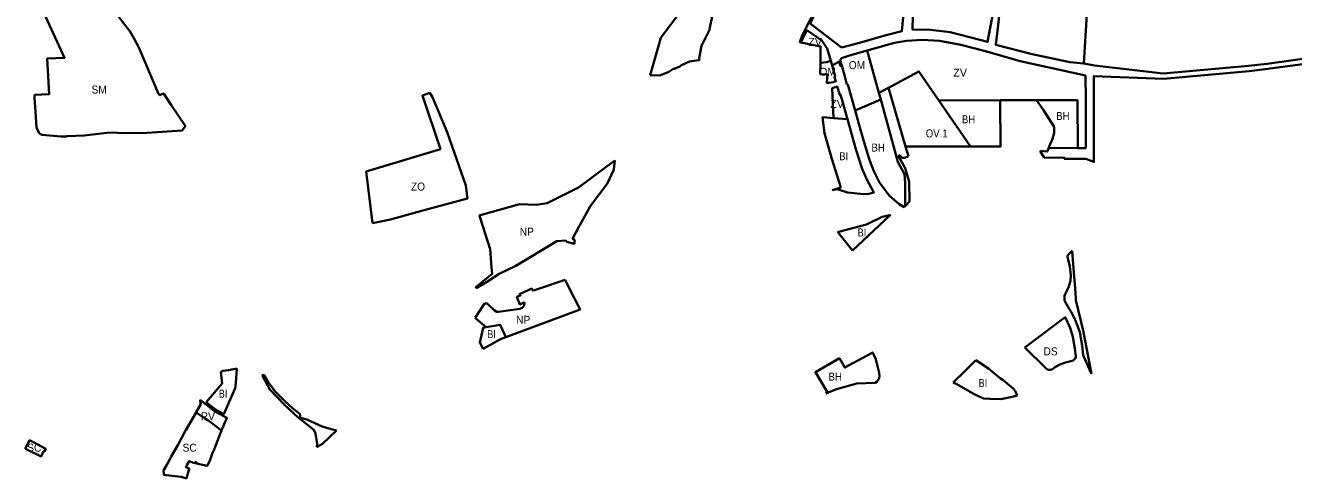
# Model space of a CAD drawing. Extents: x -650971 to -642489, y -1074311 to -1062745.
# Drawn here: x -647057 to -645155, y -1070613 to -1069933 of the extents above; entities that cross this region are included whole.
import ezdxf

# ---------------------------------------------------------------- set-up
doc = ezdxf.new("R2010")
doc.units = 0
doc.header["$LTSCALE"] = 4.8
for name, color, linetype, lineweight in [('1', 7, 'Continuous', 35), ('11', 7, 'Continuous', 35), ('12', 7, 'Continuous', 35), ('15', 7, 'Continuous', 35), ('17', 7, 'Continuous', 35), ('18', 7, 'Continuous', 35), ('2', 7, 'Continuous', 35), ('24', 7, 'Continuous', 35), ('40', 7, 'Continuous', 35), ('42', 7, 'Continuous', 35), ('48', 7, 'Continuous', 35), ('62', 7, 'Continuous', 35)]:
    doc.layers.add(name, color=color, linetype=linetype, lineweight=lineweight)

msp = doc.modelspace()

# ---------------------------------------------------------------- linework, layer by layer
at = {"layer": '1'}
for p, q in [((-645812.76, -1070060.53), (-645774.423, -1070044.167)), ((-645687.31, -1070045.724), (-645595.2, -1070045.403))]:
    msp.add_line(p, q, dxfattribs=at)
for points in [[(-645791.72, -1070133.09), (-645797.66, -1070113.88), (-645804.52, -1070089.63), (-645812.76, -1070060.53)], [(-645774.423, -1070044.167), (-645748.62, -1070137.889), (-645738.79, -1070156.281), (-645737.624, -1070169.544), (-645737.756, -1070204.389), (-645739.12, -1070205.9)], [(-645595.2, -1070045.403), (-645594.733, -1070114.868), (-645639.641, -1070114.891), (-645687.31, -1070045.724)], [(-645540.678, -1070045.406), (-645479.429, -1070045.409), (-645478.664, -1070117.114), (-645522.587, -1070116.952)], [(-645522.587, -1070116.952), (-645521.73, -1070114.83), (-645518.35, -1070106.87), (-645517.02, -1070103.08), (-645514.61, -1070094.35), (-645514.56, -1070090.91), (-645514.49, -1070085.4), (-645530.3, -1070060.08), (-645540.678, -1070045.406)], [(-645784.83, -1070151.9), (-645790.77, -1070136.14), (-645791.72, -1070133.09)], [(-645739.12, -1070205.9), (-645746.73, -1070201.04), (-645761.78, -1070188.29), (-645776.26, -1070168.94), (-645784.83, -1070151.9)], [(-645788.461, -1070424.668), (-645786.9, -1070423.81), (-645782.13, -1070432.59), (-645776.95, -1070454.51), (-645776.04, -1070459.38)], [(-645856.87, -1070485.24), (-645853.98, -1070483.81), (-645862.66, -1070469.5), (-645872.35, -1070453.55), (-645836.32, -1070432.55), (-645828.24, -1070446.54), (-645788.46, -1070424.67), (-645788.461, -1070424.668)], [(-645776.04, -1070459.38), (-645776.96, -1070462.56), (-645777.8, -1070464.4)], [(-645810.44, -1070470.17), (-645840.59, -1070479), (-645856.87, -1070485.24)], [(-645777.8, -1070464.4), (-645780.38, -1070467.64), (-645782.57, -1070469.22), (-645810.44, -1070470.17)]]:
    msp.add_lwpolyline(points, dxfattribs=at)
at = {"layer": '11'}
msp.add_lwpolyline([(-645762.868, -1070026.606), (-645717.36, -1070002.12), (-645687.31, -1070045.724), (-645639.641, -1070114.891), (-645737.075, -1070114.955)], close=True, dxfattribs=at)
at = {"layer": '12'}
for points in [[(-645864.77, -1069989.26), (-645855.54, -1069988.24), (-645849.1, -1069986.42), (-645847.14, -1069993.34), (-645844.102, -1070004.015)], [(-645833.32, -1069991.86), (-645835, -1069985), (-645833, -1069982), (-645821, -1069978), (-645794.679, -1069970.596), (-645777.143, -1070034.287), (-645774.423, -1070044.167), (-645812.76, -1070060.53)], [(-645855.168, -1070019.44), (-645855.17, -1070019.44), (-645854.42, -1070006.47), (-645864.97, -1070006.16), (-645864.77, -1069989.26)], [(-645844.102, -1070004.015), (-645843.22, -1070007.12), (-645842.8, -1070008.59)], [(-645825.08, -1070021.52), (-645828.9, -1070007.76), (-645833.32, -1069991.86)], [(-645841.92, -1070017.321), (-645841.89, -1070017.42), (-645845.17, -1070017.91), (-645845.14, -1070018.08), (-645845.37, -1070018.12), (-645852.33, -1070019.2), (-645852.36, -1070019.01), (-645855.168, -1070019.44)], [(-645842.8, -1070008.59), (-645843.94, -1070010.6), (-645841.92, -1070017.321)], [(-645812.76, -1070060.53), (-645823.76, -1070021.67), (-645825.08, -1070021.52)]]:
    msp.add_lwpolyline(points, dxfattribs=at)
at = {"layer": '15'}
msp.add_line((-646701.65, -1070457.93), (-646699.26, -1070457.2), dxfattribs=at)
for points in [[(-645857.204, -1069862.954), (-645857.289, -1069863.338), (-645863.95, -1069889.468), (-645869.262, -1069905.935), (-645874.219, -1069917.496), (-645880.431, -1069930.3), (-645833, -1069966), (-645806, -1069959), (-645768.424, -1069948.431), (-645742.967, -1069941.862), (-645738.039, -1069894.231), (-645729.006, -1069844.136), (-645777.852, -1069832.241), (-645804.185, -1069825.84), (-645804.28, -1069826.76)], [(-645894.25, -1069958.7), (-645895.66, -1069958.42), (-645892.09, -1069947.98), (-645876.15, -1069916.47), (-645870.89, -1069903.5), (-645865.78, -1069888.76), (-645858.78, -1069862.84), (-645857.204, -1069862.954)], [(-645464.288, -1069895.362), (-645492.842, -1069895), (-645526.451, -1069890.745), (-645589.84, -1069875.892), (-645594.866, -1069902.242), (-645596.463, -1069914.335), (-645598.491, -1069932.472), (-645601.753, -1069962.317), (-645547.4, -1069976.382), (-645490.814, -1069988.074), (-645469.701, -1069990.011)], [(-645849.1, -1069986.42), (-645854.81, -1069967.927), (-645862.782, -1069955.809), (-645885.422, -1069940.184), (-645894.25, -1069958.7)], [(-645478.664, -1070117.114), (-645466.96, -1070117.157), (-645467.068, -1070044.959), (-645467.472, -1070008.38), (-645565.133, -1069986.508), (-645617.403, -1069971.714), (-645654.145, -1069962.232), (-645686.147, -1069956.306), (-645712.222, -1069954.725), (-645735.532, -1069956.306), (-645753.706, -1069959.071), (-645794.679, -1069970.596)], [(-645794.679, -1069970.596), (-645821, -1069978), (-645833, -1069982), (-645835, -1069985), (-645833.32, -1069991.86), (-645834.65, -1069994.21), (-645836.64, -1069987.18), (-645847.14, -1069993.34), (-645849.1, -1069986.42)], [(-645004.791, -1070324.889), (-645034.122, -1070126.616), (-645043.92, -1070076.344), (-645050.293, -1070047.035), (-645056.555, -1070026.163), (-645065.235, -1070011.695), (-645086.484, -1069984.195), (-645123.206, -1069988.629), (-645194.003, -1069998.417), (-645221.99, -1070001.66), (-645350.591, -1070013.242), (-645455.073, -1070009.111), (-645454.881, -1070137.836), (-645466.862, -1070133.219), (-645499.142, -1070133.293)], [(-645469.701, -1069990.011), (-645453.852, -1069992.968), (-645350.784, -1070005.227), (-645222.809, -1069993.701), (-645195.011, -1069990.48), (-645124.233, -1069980.695), (-645064.052, -1069973.429)], [(-645777.143, -1070034.287), (-645762.868, -1070026.606), (-645737.075, -1070114.955), (-645732.91, -1070129.5)], [(-645737.756, -1070204.389), (-645737.624, -1070169.544), (-645738.79, -1070156.281), (-645748.62, -1070137.889), (-645774.423, -1070044.167), (-645777.143, -1070034.287)], [(-645534.63, -1070121.09), (-645524.82, -1070122.48), (-645522.587, -1070116.952), (-645478.664, -1070117.114)], [(-645732.91, -1070129.5), (-645734.77, -1070130.18), (-645737.48, -1070131.45), (-645738.41, -1070131.78), (-645739.41, -1070131.93), (-645740.89, -1070131.8), (-645741.83, -1070131.53), (-645742.67, -1070131.07), (-645743.87, -1070130.15), (-645744.73, -1070129), (-645745.29, -1070127.83), (-645747.67, -1070129.14), (-645737.63, -1070147.39), (-645731.94, -1070167.87), (-645731.3, -1070197.24), (-645737.756, -1070204.389)], [(-645529.17, -1070131.4), (-645534.7, -1070122.95), (-645534.63, -1070121.09)], [(-645499.142, -1070133.293), (-645499.276, -1070131.652), (-645529.17, -1070131.4)], [(-645491.97, -1070358.14), (-645496.02, -1070351.15), (-645498, -1070347.74), (-645498.74, -1070345.87), (-645499.09, -1070343.91), (-645499.01, -1070340.96), (-645498.75, -1070338.98), (-645497.83, -1070336.16), (-645496.12, -1070332.34), (-645495.44, -1070330.67), (-645493.05, -1070326.11), (-645490.03, -1070316.27), (-645489.31, -1070307.77), (-645490.79, -1070294.93), (-645494.12, -1070282.52), (-645494.57, -1070280.34), (-645493.8, -1070277.67), (-645491.94, -1070275.85), (-645487.361, -1070271.37)], [(-645487.361, -1070271.37), (-645485.21, -1070298.03), (-645484.27, -1070309.7), (-645483.34, -1070321.17), (-645481.65, -1070342.07), (-645481.67, -1070345.39), (-645471, -1070391), (-645458.32, -1070455.91)], [(-645458.32, -1070455.91), (-645461.32, -1070449.31), (-645470.99, -1070428.07), (-645472.61, -1070413.13), (-645476.12, -1070393.13), (-645482.16, -1070375.96), (-645488.99, -1070362.96), (-645491.97, -1070358.14)], [(-646643.895, -1070524.284), (-646647.226, -1070521.673), (-646668.361, -1070502.459), (-646690.316, -1070479.212), (-646693.119, -1070474.009), (-646701.65, -1070457.93)], [(-646699.26, -1070457.2), (-646692.74, -1070468.28), (-646681.6, -1070482.89), (-646667.42, -1070497.28)], [(-646800.94, -1070514.04), (-646800.6, -1070513.43), (-646793.75, -1070501.26), (-646794.53, -1070495.7), (-646794.59, -1070494.62)], [(-646794.59, -1070494.62), (-646773, -1070511.96), (-646770.95, -1070512.94), (-646765.96, -1070515.75), (-646754.52, -1070522.08), (-646755.84, -1070524.5), (-646762.71, -1070540.85)], [(-646667.42, -1070497.28), (-646656.83, -1070506.66), (-646656.09, -1070507.31)], [(-646762.71, -1070540.85), (-646779.68, -1070527.87), (-646782.63, -1070526.02), (-646788, -1070522.49), (-646800.94, -1070514.04)], [(-646656.09, -1070507.31), (-646653.87, -1070509.28), (-646645.31, -1070515.85), (-646644.2, -1070522.08)], [(-646644.2, -1070522.08), (-646634.85, -1070524.43), (-646611.88, -1070534.82), (-646599.81, -1070538.51), (-646590.2, -1070540.66)], [(-646619.99, -1070565.54), (-646619.34, -1070560.95), (-646621.729, -1070545.248), (-646624.211, -1070539.711), (-646643.895, -1070524.284)], [(-646590.2, -1070540.66), (-646611.41, -1070560.96), (-646619.15, -1070565.53), (-646619.99, -1070565.54)]]:
    msp.add_lwpolyline(points, dxfattribs=at)
msp.add_lwpolyline([(-645599.271, -1069873.685), (-645677.849, -1069855.3), (-645716.277, -1069847.01), (-645723.668, -1069891.356), (-645726.131, -1069918.457), (-645726.542, -1069939.398), (-645699.889, -1069939.714), (-645670.325, -1069943.002), (-645625.979, -1069954.92), (-645614.072, -1069957.797), (-645606.07, -1069913.163), (-645604.424, -1069900.701)], close=True, dxfattribs=at)
at = {"layer": '17'}
msp.add_line((-646849.59, -1070607.4), (-646848.99, -1070606.28), dxfattribs=at)
for points in [[(-646816.42, -1070540.49), (-646802.19, -1070516.26), (-646800.94, -1070514.04)], [(-646800.94, -1070514.04), (-646788, -1070522.49), (-646782.63, -1070526.02), (-646779.68, -1070527.87), (-646762.71, -1070540.85)], [(-646848.99, -1070606.28), (-646849.72, -1070600.98), (-646844.76, -1070592.54), (-646841.16, -1070585.79), (-646838.95, -1070581.53), (-646838.05, -1070579.93), (-646828.45, -1070562.89), (-646816.6, -1070540.84), (-646816.42, -1070540.49)], [(-646762.71, -1070540.85), (-646763.68, -1070543.15), (-646764.24, -1070544.5), (-646768.86, -1070556.21), (-646771.17, -1070562.7), (-646774.91, -1070571.88), (-646775.25, -1070572.39)], [(-646775.25, -1070572.39), (-646776.04, -1070574.27), (-646779.9, -1070584.92), (-646783.59, -1070593.52), (-646784, -1070593.34), (-646784.18, -1070593.76), (-646800.47, -1070590.28), (-646800.13, -1070588.71), (-646801.73, -1070588.37), (-646802.06, -1070589.93), (-646806.41, -1070589), (-646811.06, -1070586.67), (-646814.52, -1070592.78), (-646816.11, -1070595.8), (-646814.95, -1070596.36), (-646810.82, -1070598.23), (-646811.5, -1070600.29), (-646812.5, -1070603.78), (-646813.97, -1070608.7), (-646815.05, -1070613.14)], [(-646815.05, -1070613.14), (-646822.99, -1070610.51), (-646827.88, -1070610.12), (-646849.59, -1070607.4)]]:
    msp.add_lwpolyline(points, dxfattribs=at)
msp.add_lwpolyline([(-647055.79, -1070569.07), (-647056.8, -1070568.32), (-647056.79, -1070567.41), (-647052.77, -1070559.7), (-647051.14, -1070556.59), (-647050.37, -1070555.74), (-647049.52, -1070555.64), (-647026.14, -1070568.26), (-647028.52, -1070572.63), (-647029.44, -1070572.13), (-647033.01, -1070579.83)], close=True, dxfattribs=at)
at = {"layer": '18'}
for points in [[(-647043.25, -1070037.29), (-647021.27, -1070036.28), (-647024.05, -1069982.48), (-646998.06, -1069981.49), (-647034.51, -1069902.21)], [(-646931.67, -1069902.89), (-646922.79, -1069912.31), (-646909.48, -1069929.65), (-646900.26, -1069941.64), (-646894.42, -1069952.39), (-646886.85, -1069966.26), (-646857.06, -1070035.86), (-646855.62, -1070037.66), (-646849.79, -1070035.17), (-646849.33, -1070035.63), (-646837.65, -1070053.22), (-646816.9, -1070084.45), (-646817.15, -1070084.76)], [(-647036.03, -1070094.96), (-647040.12, -1070086.11), (-647040.92, -1070070.85), (-647041.53, -1070062.28), (-647043.03, -1070042.14), (-647043.25, -1070037.29)], [(-646817.15, -1070084.76), (-646821.89, -1070090.7), (-646859.29, -1070093.1), (-646874.9, -1070094.1), (-646904.97, -1070094.52), (-646918.75, -1070094.08), (-646925.08, -1070093.82), (-646934.63, -1070094.24), (-646968.89, -1070098.02), (-646993.92, -1070099.49), (-646995.86, -1070099.52), (-647003.49, -1070099.66), (-647031.73, -1070097.21), (-647034.17, -1070096.49), (-647036.03, -1070094.96)]]:
    msp.add_lwpolyline(points, dxfattribs=at)
at = {"layer": '2'}
msp.add_line((-645665.6, -1070469.04), (-645648.9, -1070452.38), dxfattribs=at)
for points in [[(-645804.28, -1069826.76), (-645804.185, -1069825.84), (-645777.852, -1069832.241), (-645729.006, -1069844.136), (-645738.039, -1069894.231), (-645742.967, -1069941.862), (-645768.424, -1069948.431), (-645806, -1069959), (-645833, -1069966), (-645880.431, -1069930.3), (-645874.219, -1069917.496), (-645869.262, -1069905.935), (-645863.95, -1069889.468), (-645857.289, -1069863.338), (-645857.204, -1069862.954)], [(-645469.701, -1069990.011), (-645490.814, -1069988.074), (-645547.4, -1069976.382), (-645601.753, -1069962.317), (-645598.491, -1069932.472), (-645596.463, -1069914.335), (-645594.866, -1069902.242), (-645589.84, -1069875.892), (-645526.451, -1069890.745), (-645492.842, -1069895), (-645464.288, -1069895.362)], [(-645464.288, -1069895.362), (-645464.206, -1069899.449), (-645469.701, -1069990.011)], [(-645858.53, -1070094.64), (-645861.74, -1070070.95), (-645855.28, -1070071.32), (-645845.01, -1070072.12), (-645824.28, -1070073.67), (-645811.48, -1070118.65), (-645801.99, -1070148.51), (-645795.07, -1070164.26), (-645784.51, -1070183.77), (-645792.37, -1070186.01)], [(-645847.2, -1070180.14), (-645834.31, -1070176.15), (-645847.88, -1070133.4), (-645858.53, -1070094.64)], [(-645792.37, -1070186.01), (-645799.91, -1070186.32), (-645824.12, -1070183.63), (-645839.82, -1070178.94), (-645847.2, -1070180.14)], [(-645833.92, -1070241.96), (-645795.85, -1070231.81), (-645772.08, -1070220.39), (-645760.91, -1070217.98)], [(-645760.91, -1070217.98), (-645760.05, -1070217.79), (-645816.9, -1070270.96)], [(-645816.9, -1070270.96), (-645838.53, -1070243.19), (-645833.92, -1070241.96)], [(-646370.56, -1070418.29), (-646375.63, -1070408.76), (-646370.61, -1070386.73), (-646365.7, -1070385.89)], [(-646365.7, -1070385.89), (-646344.93, -1070382.33), (-646336.35, -1070400.9)], [(-646336.35, -1070400.9), (-646344.26, -1070403.84), (-646370.56, -1070418.29)], [(-645648.9, -1070452.38), (-645636.42, -1070439.93), (-645631.63, -1070435.3)], [(-645631.63, -1070435.3), (-645612.77, -1070447.82), (-645594.62, -1070462.7), (-645590.966, -1070465.607), (-645575.7, -1070477.77), (-645572.86, -1070481.41), (-645569.97, -1070488.3)], [(-646785.5, -1070498.47), (-646785.15, -1070498.05), (-646761.8, -1070470.4), (-646763.94, -1070452.95)], [(-646763.94, -1070452.95), (-646760.03, -1070451.56), (-646752.29, -1070450.28), (-646739.74, -1070447.98)], [(-646739.74, -1070447.98), (-646741.33, -1070469.79), (-646742.37, -1070477.2), (-646747.89, -1070489.87), (-646759.42, -1070516.37)], [(-645569.97, -1070488.3), (-645571.13, -1070488.89), (-645577.47, -1070490.3), (-645594.41, -1070494.08), (-645610.16, -1070493.43), (-645611.52, -1070493.37), (-645620.22, -1070493), (-645633.35, -1070486.91), (-645660.29, -1070471.12), (-645665.6, -1070469.04)], [(-646759.42, -1070516.37), (-646771.9, -1070509.4), (-646785.5, -1070498.47)]]:
    msp.add_lwpolyline(points, dxfattribs=at)
msp.add_lwpolyline([(-645599.271, -1069873.685), (-645604.424, -1069900.701), (-645606.07, -1069913.163), (-645614.072, -1069957.797), (-645625.979, -1069954.92), (-645670.325, -1069943.002), (-645699.889, -1069939.714), (-645726.542, -1069939.398), (-645726.131, -1069918.457), (-645723.668, -1069891.356), (-645716.277, -1069847.01), (-645677.849, -1069855.3)], close=True, dxfattribs=at)
at = {"layer": '24'}
for points in [[(-645558.36, -1070416.1), (-645497.81, -1070370.93), (-645490.19, -1070386.97)], [(-645490.19, -1070386.97), (-645486.54, -1070400.38), (-645483.29, -1070417.99)], [(-645483.29, -1070417.99), (-645481.93, -1070430.04), (-645482.18, -1070432.13), (-645485.67, -1070435.7), (-645489.34, -1070437.05), (-645497.33, -1070438.82), (-645505.88, -1070441.74), (-645513.81, -1070446.24), (-645517.44, -1070449.23), (-645517.95, -1070449.45), (-645520.4, -1070449.87), (-645521.41, -1070449.84), (-645522.95, -1070449.61), (-645524.42, -1070449.16), (-645525.75, -1070448.41), (-645527.34, -1070447.1), (-645558.36, -1070416.1)]]:
    msp.add_lwpolyline(points, dxfattribs=at)
at = {"layer": '40'}
for points in [[(-645894.25, -1069958.7), (-645885.422, -1069940.184), (-645862.782, -1069955.809), (-645854.81, -1069967.927), (-645849.1, -1069986.42)], [(-645864.77, -1069989.26), (-645864.48, -1069964.53), (-645894.25, -1069958.7)], [(-645794.679, -1069970.596), (-645753.706, -1069959.071), (-645735.532, -1069956.306), (-645712.222, -1069954.725), (-645686.147, -1069956.306), (-645654.145, -1069962.232), (-645617.403, -1069971.714), (-645565.133, -1069986.508), (-645467.472, -1070008.38), (-645467.068, -1070044.959), (-645466.96, -1070117.157), (-645478.664, -1070117.114)], [(-645849.1, -1069986.42), (-645855.54, -1069988.24), (-645864.77, -1069989.26)], [(-645687.31, -1070045.724), (-645717.36, -1070002.12), (-645762.868, -1070026.606), (-645777.143, -1070034.287), (-645794.679, -1069970.596)], [(-645540.678, -1070045.406), (-645547.768, -1070045.237), (-645595.2, -1070045.403), (-645687.31, -1070045.724)], [(-645478.664, -1070117.114), (-645479.429, -1070045.409), (-645540.678, -1070045.406)]]:
    msp.add_lwpolyline(points, dxfattribs=at)
msp.add_lwpolyline([(-645847.08, -1070027.09), (-645839.641, -1070024.9), (-645835.91, -1070037.31), (-645834.8, -1070036.71), (-645824.28, -1070073.67), (-645845.01, -1070072.12)], close=True, dxfattribs=at)
at = {"layer": '42'}
for points in [[(-646536.47, -1070229.65), (-646545.78, -1070152.41), (-646434.503, -1070118.512), (-646461.415, -1070037.991), (-646450.22, -1070034.31)], [(-646450.22, -1070034.31), (-646446.21, -1070040.55), (-646424.17, -1070093.21), (-646417.23, -1070113.25), (-646396.51, -1070173.06), (-646393.97, -1070192.69), (-646460.8, -1070210.57), (-646509.31, -1070224.11), (-646536.47, -1070229.65)]]:
    msp.add_lwpolyline(points, dxfattribs=at)
at = {"layer": '48'}
for points in [[(-646119.95, -1070007.73), (-646104.04, -1069951.75), (-646077.78, -1069916.11)], [(-646027.3, -1069919.47), (-646030.62, -1069936.3), (-646031.24, -1069939.45), (-646043.2, -1069963.46), (-646046.63, -1069982.04), (-646046.28, -1069985.18)], [(-646046.28, -1069985.18), (-646050.68, -1069985.78), (-646060.94, -1069987.19), (-646073.1, -1069992.61), (-646075.69, -1069994.68), (-646083.67, -1069998.4), (-646084.39, -1069997.53), (-646091.87, -1070002.66), (-646105.35, -1070008.18), (-646119.95, -1070007.73)], [(-646376.5, -1070218.32), (-646315.95, -1070201.09), (-646291.14, -1070202.1), (-646274.26, -1070199.6), (-646227.29, -1070176.24), (-646173.2, -1070135.64)], [(-646173.2, -1070135.64), (-646174.62, -1070149.28), (-646184.67, -1070170.61), (-646209.55, -1070203.85), (-646225.7, -1070232.93), (-646226.42, -1070234.23), (-646236.44, -1070253.13), (-646233.06, -1070254.74), (-646233.36, -1070257.04), (-646233.69, -1070259.57)], [(-646380.69, -1070327.47), (-646381.25, -1070325.85), (-646356.8, -1070305.73), (-646357.73, -1070296.13), (-646359.89, -1070269.01), (-646375.52, -1070220.21), (-646376.5, -1070218.32)], [(-646233.69, -1070259.57), (-646234.17, -1070260.88), (-646245.02, -1070257.65), (-646246.71, -1070255.96), (-646259.91, -1070256.89), (-646321.24, -1070293.85), (-646346.57, -1070305.88), (-646365.63, -1070318.37), (-646380.69, -1070327.47)], [(-646382.67, -1070371.94), (-646368.4, -1070350.41), (-646364.34, -1070350.19), (-646353.81, -1070360.18), (-646349.76, -1070362.69), (-646347.49, -1070363.01), (-646315.7, -1070358.27), (-646314.6, -1070358.05), (-646311.82, -1070356.89), (-646309.99, -1070354.58), (-646309.18, -1070352.77), (-646308.59, -1070350.22), (-646308.791, -1070348.855), (-646315.46, -1070351.67), (-646316.59, -1070348.85), (-646318.44, -1070344.2), (-646319.95, -1070340.42), (-646314.84, -1070338.41), (-646315.84, -1070336.13), (-646297.4, -1070328.01), (-646296.13, -1070330.88), (-646295.99, -1070330.85), (-646293.14, -1070330.3), (-646290.48, -1070329.41), (-646247.667, -1070315.004)], [(-646247.667, -1070315.004), (-646242.56, -1070325.1), (-646225.15, -1070359.46), (-646336.35, -1070400.9)], [(-646336.35, -1070400.9), (-646344.93, -1070382.33), (-646365.7, -1070385.89), (-646377.86, -1070375.71), (-646382.67, -1070371.94)]]:
    msp.add_lwpolyline(points, dxfattribs=at)

# ---------------------------------------------------------------- texts
at = {"layer": '62'}
for s, p in [('ZV', (-645883.022, -1069963.776)), ('ZV', (-645665.601, -1070009.978)), ('ZV', (-645850.022, -1070056.776)), ('PV', (-646793.831, -1070525.433))]:
    msp.add_text(s, height=12, dxfattribs=at).set_placement(p)
for s, width, p in [('OM', 0.95, (-645822.28, -1069998.561)), ('OM', 0.95, (-645866.28, -1070008.561)), ('SM', 0.95, (-646957.615, -1070035.352)), ('BH', 0.9, (-645652.699, -1070079.977)), ('BH', 0.9, (-645511.328, -1070074.977)), ('OV.1', 0.9, (-645706.926, -1070101.134)), ('BH', 0.9, (-645788.337, -1070122.32)), ('BI', 0.85, (-645836.337, -1070135.32)), ('ZO', 0.95, (-646478.758, -1070180.853)), ('NP', 0.95, (-646315.631, -1070248.579)), ('BI', 0.85, (-645808.987, -1070249.726)), ('NP', 0.95, (-646320.99, -1070380.819)), ('BI', 0.85, (-646364.337, -1070402.32)), ('DS', 0.95, (-645530.386, -1070428.148)), ('BH', 0.9, (-645852.646, -1070466.101)), ('BI', 0.85, (-646766.828, -1070491.569)), ('BI', 0.85, (-645627.657, -1070475.713)), ('SC', 0.95, (-647054.06, -1070572.645)), ('SC', 0.95, (-646821.06, -1070572.645))]:
    msp.add_text(s, height=12, dxfattribs=dict(at, width=width)).set_placement(p)

doc.saveas('drawing.dxf')
